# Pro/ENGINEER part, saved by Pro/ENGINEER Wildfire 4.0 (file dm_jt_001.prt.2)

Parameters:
  METRIC = "NO"

Other parameters: PITCH, DRILL_DIAMETER, THREAD_DIAMETER, THREADS_PER_INCH, THREAD_DEPTH, THREAD_LENGTH, DRILL_POINT_ANGLE, DRILL_DEPTH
